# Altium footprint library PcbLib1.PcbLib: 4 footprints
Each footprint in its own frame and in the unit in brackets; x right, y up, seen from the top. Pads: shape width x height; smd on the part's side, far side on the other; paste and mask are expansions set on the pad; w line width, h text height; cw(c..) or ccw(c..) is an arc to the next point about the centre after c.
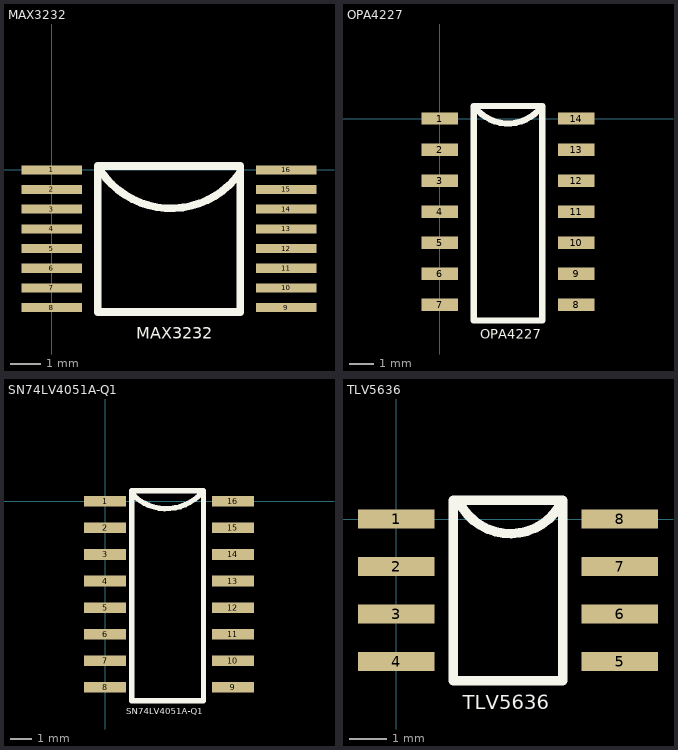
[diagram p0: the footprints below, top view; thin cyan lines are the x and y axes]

## MAX3232 [mm]
pads (16):
  rect 2x0.3 smd: 1(0,0) 2(0,-0.65) 3(0,-1.3) 4(0,-1.95) 5(0,-2.6) 6(0,-3.25) 7(0,-3.9) 8(0,-4.55) 9(7.747,-4.55) 10(7.747,-3.9) 11(7.747,-3.25) 12(7.747,-2.6) 13(7.747,-1.95) 14(7.747,-1.3) 15(7.747,-0.65) 16(7.747,0)
Top Overlay:
  lines w0.254: 1.61,-0.027 ccw(c3.937,1.524) 6.222,-0.089 ; 1.524,-4.699 1.524,0.127 6.223,0.127 6.223,-4.699 1.524,-4.699
  text "MAX3232" at 2.794,-5.588 h0.38

## OPA4227 [mm]
pads (14):
  rect 1.5x0.51 smd: 1(0,0) 2(0,-1.27) 3(0,-2.54) 4(0,-3.81) 5(0,-5.08) 6(0,-6.35) 7(0,-7.62) 8(5.588,-7.62) 9(5.588,-6.35) 10(5.588,-5.08) 11(5.588,-3.81) 12(5.588,-2.54) 13(5.588,-1.27) 14(5.588,0)
Top Overlay:
  lines w0.254: 1.397,0.508 ccw(c2.794,1.524) 4.191,0.508 ; 1.397,0.508 1.397,-8.255 4.191,-8.255 4.191,0.508 ; 1.397,0.508 4.191,0.508
  text "OPA4227" at 1.651,-9.017 h0.38

## SN74LV4051A-Q1 [mm]
pads (16):
  rect 2x0.51 smd: 1(0,0) 2(0,-1.27) 3(0,-2.54) 4(0,-3.81) 5(0,-5.08) 6(0,-6.35) 7(0,-7.62) 8(0,-8.89) 9(6.096,-8.89) 10(6.096,-7.62) 11(6.096,-6.35) 12(6.096,-5.08) 13(6.096,-3.81) 14(6.096,-2.54) 15(6.096,-1.27) 16(6.096,0)
Top Overlay:
  lines w0.254: 1.259,0.371 ccw(c2.921,1.905) 4.638,0.433 ; 1.27,-9.525 1.27,0.508 4.699,0.508 4.699,-9.525 1.27,-9.525
  text "SN74LV4051A-Q1" at 1.016,-10.16 h0.3

## TLV5636 [mm]
pads (8):
  rect 2.05x0.51 smd: 1(0,0) 2(0,-1.27) 3(0,-2.54) 4(0,-3.81) 5(5.969,-3.81) 6(5.969,-2.54) 7(5.969,-1.27) 8(5.969,0)
Top Overlay:
  lines w0.254: 1.675,0.457 ccw(c3.048,1.143) 4.445,0.508 ; 4.445,0.508 1.524,0.508 1.524,-4.318 4.445,-4.318 4.445,0.508
  text "TLV5636" at 1.778,-5.08 h0.38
